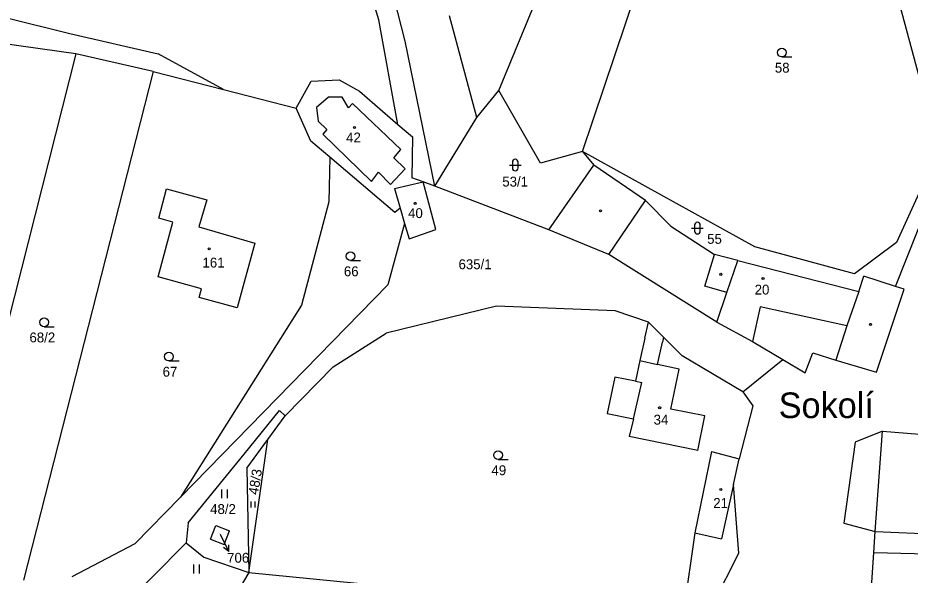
# Model space of a CAD drawing. Extents: x -654459 to -653618, y -1151040 to -1150446.
# Drawn here: x -654178.6 to -654025.1, y -1150881.9 to -1150786 of the extents above; entities that cross this region are included whole.
import ezdxf

# ---------------------------------------------------------------- set-up
doc = ezdxf.new("R2010")
doc.units = 0
for name, color, linetype in [('Vrstva 1', 7, 'Continuous'), ('Vrstva 13', 7, 'Continuous'), ('Vrstva 2', 7, 'Continuous'), ('Vrstva 3', 7, 'Continuous'), ('Vrstva 4', 7, 'Continuous'), ('Vrstva 5', 7, 'Continuous'), ('Vrstva 7', 7, 'Continuous')]:
    doc.layers.add(name, color=color, linetype=linetype)

msp = doc.modelspace()

# ---------------------------------------------------------------- linework, layer by layer
at = {"layer": 'Vrstva 1'}
for points in [[(-654309.16, -1150753.96), (-654169.59, -1150788.7)], [(-654111.94, -1150790.03), (-654117.57, -1150767.99)], [(-654116.45, -1150786.36), (-654121.45, -1150769.94)], [(-654081.45, -1150808.97), (-654068.36, -1150770.11)], [(-654095.8, -1150798.49), (-654088.98, -1150781.92)], [(-654021.7, -1150802.89), (-654026.75, -1150784.17)], [(-654113.16, -1150804.35), (-654116.45, -1150786.36)], [(-654099.58, -1150803.17), (-654104.28, -1150785.64)], [(-654169.59, -1150788.7), (-654154.41, -1150792.18)], [(-654168.58, -1150792.21), (-654181.23, -1150790.41)], [(-654106.85, -1150814.94), (-654111.94, -1150790.03)], [(-654168.58, -1150792.21), (-654186.2, -1150861.52)], [(-654155.27, -1150795.25), (-654168.58, -1150792.21)], [(-654143.15, -1150798.35), (-654154.41, -1150792.18)], [(-654155.27, -1150795.25), (-654177.57, -1150882.76)], [(-654155.27, -1150795.25), (-654143.15, -1150798.35)], [(-654130.65, -1150801.54), (-654128.09, -1150796.9)], [(-654128.09, -1150796.9), (-654123.29, -1150796.64)], [(-654123.29, -1150796.64), (-654119.76, -1150798.64)], [(-654143.15, -1150798.35), (-654130.65, -1150801.54)], [(-654119.76, -1150798.64), (-654113.16, -1150804.35)], [(-654099.58, -1150803.17), (-654095.8, -1150798.49)], [(-654088.62, -1150811.01), (-654095.8, -1150798.49)], [(-654128.14, -1150807.23), (-654130.65, -1150801.54)], [(-654106.85, -1150814.94), (-654099.58, -1150803.17)], [(-654113.16, -1150804.35), (-654110.68, -1150806.5)], [(-654110.68, -1150806.5), (-654110.79, -1150813.55)], [(-654124.87, -1150810), (-654128.14, -1150807.23)], [(-654020.03, -1150808.4), (-654027.41, -1150824.64)], [(-654081.45, -1150808.97), (-654088.62, -1150811.01)], [(-654051.79, -1150825.38), (-654081.45, -1150808.97)], [(-654081.45, -1150808.97), (-654079.5, -1150811.32)], [(-654027.56, -1150832.2), (-654018.25, -1150808.73)], [(-654124.87, -1150810), (-654125.04, -1150817.67)], [(-654113.68, -1150819.5), (-654124.87, -1150810)], [(-654087.23, -1150822.49), (-654079.5, -1150811.32)], [(-654070.58, -1150817.41), (-654079.5, -1150811.32)], [(-654113.77, -1150815.37), (-654108.85, -1150814.2)], [(-654108.85, -1150814.2), (-654110.79, -1150813.55)], [(-654106.63, -1150822.43), (-654108.85, -1150814.2)], [(-654106.85, -1150814.94), (-654108.85, -1150814.2)], [(-654154.32, -1150820.47), (-654152.98, -1150815.43)], [(-654152.98, -1150815.43), (-654146.07, -1150817.3)], [(-654113.77, -1150815.37), (-654112.79, -1150818.74)], [(-654087.23, -1150822.49), (-654106.85, -1150814.94)], [(-654146.07, -1150817.3), (-654147.44, -1150821.94)], [(-654070.58, -1150817.41), (-654066.24, -1150821.87)], [(-654125.04, -1150817.67), (-654129.75, -1150835.46)], [(-654112.79, -1150818.74), (-654113.68, -1150819.5)], [(-654112.79, -1150818.74), (-654112.02, -1150821.38)], [(-654151.9, -1150821.13), (-654154.32, -1150820.47)], [(-654154.44, -1150830.58), (-654151.9, -1150821.13)], [(-654147.44, -1150821.94), (-654137.76, -1150824.79)], [(-654112.02, -1150821.38), (-654114.9, -1150831.92)], [(-654112.02, -1150821.38), (-654111.24, -1150824.03)], [(-654066.24, -1150821.87), (-654058.69, -1150826.71)], [(-654111.24, -1150824.03), (-654106.63, -1150822.43)], [(-654076.92, -1150826.7), (-654087.23, -1150822.49)], [(-654137.76, -1150824.79), (-654140.8, -1150835.92)], [(-654027.41, -1150824.64), (-654034.63, -1150830.06)], [(-654058.32, -1150838.34), (-654076.92, -1150826.7)], [(-654054.69, -1150827.74), (-654058.69, -1150826.71)], [(-654034.63, -1150830.06), (-654051.79, -1150825.38)], [(-654054.69, -1150827.74), (-654033.91, -1150833.09)], [(-654146.96, -1150832.63), (-654154.44, -1150830.58)], [(-654033.91, -1150833.09), (-654033.02, -1150830.45)], [(-654027.56, -1150832.2), (-654033.02, -1150830.45)], [(-654114.9, -1150831.92), (-654150.57, -1150868.48)], [(-654147.35, -1150834.1), (-654146.96, -1150832.63)], [(-654030.83, -1150846.98), (-654026.12, -1150832.7)], [(-654026.12, -1150832.7), (-654027.56, -1150832.2)], [(-654140.8, -1150835.92), (-654147.35, -1150834.1)], [(-654129.75, -1150835.46), (-654150.57, -1150868.48)], [(-654096.24, -1150835.59), (-654115.19, -1150840.24)], [(-654075.8, -1150836.41), (-654096.24, -1150835.59)], [(-654070.09, -1150838.34), (-654075.8, -1150836.41)], [(-654070.7, -1150841.13), (-654070.09, -1150838.34)], [(-654070.09, -1150838.34), (-654067.48, -1150840.96)], [(-654058.32, -1150838.34), (-654052.21, -1150841.67)], [(-654124.32, -1150846.07), (-654115.19, -1150840.24)], [(-654070.7, -1150841.13), (-654071.54, -1150844.98)], [(-654068.5, -1150845.64), (-654067.66, -1150841.79)], [(-654067.48, -1150840.96), (-654067.66, -1150841.79)], [(-654067.48, -1150840.96), (-654064.28, -1150844.18)], [(-654052.21, -1150841.67), (-654046.97, -1150844.79)], [(-654043.1, -1150847.09), (-654041.8, -1150843.63)], [(-654041.8, -1150843.63), (-654037.86, -1150844.88)], [(-654071.54, -1150844.98), (-654072.32, -1150848.54)], [(-654053.85, -1150850.35), (-654064.28, -1150844.18)], [(-654053.85, -1150850.35), (-654046.97, -1150844.79)], [(-654046.97, -1150844.79), (-654043.1, -1150847.09)], [(-654037.86, -1150844.88), (-654030.83, -1150846.98)], [(-654132.59, -1150854.45), (-654124.32, -1150846.07)], [(-654064.77, -1150846.44), (-654068.5, -1150845.64)], [(-654066.25, -1150853.31), (-654064.77, -1150846.44)], [(-654075.89, -1150847.81), (-654077.17, -1150854.09)], [(-654072.32, -1150848.54), (-654075.89, -1150847.81)], [(-654053.85, -1150850.35), (-654052.1, -1150852.78)], [(-654052.1, -1150852.78), (-654054.47, -1150861.9)], [(-654139.6, -1150861.05), (-654133.55, -1150853.57)], [(-654135.57, -1150858.56), (-654132.59, -1150854.45)], [(-654133.55, -1150853.57), (-654132.59, -1150854.45)], [(-654077.17, -1150854.09), (-654072.67, -1150855.01)], [(-654060.37, -1150854.49), (-654066.25, -1150853.31)], [(-654072.67, -1150855.01), (-654073.37, -1150858.06)], [(-654061.57, -1150860.44), (-654060.37, -1150854.49)], [(-654029.83, -1150857.12), (-654034.52, -1150859)], [(-654029.83, -1150857.12), (-654002.97, -1150859.28)], [(-654139.15, -1150863.5), (-654135.57, -1150858.56)], [(-654138.81, -1150881.42), (-654135.57, -1150858.56)], [(-654061.57, -1150860.44), (-654073.37, -1150858.06)], [(-654034.52, -1150859), (-654036.45, -1150872.93)], [(-654149.26, -1150872.9), (-654139.6, -1150861.05)], [(-654059.26, -1150860.62), (-654062.12, -1150874.59)], [(-654059.26, -1150860.62), (-654054.47, -1150861.9)], [(-654055.44, -1150866.28), (-654054.47, -1150861.9)], [(-654139.15, -1150863.5), (-654138.81, -1150881.42)], [(-654054.51, -1150878.1), (-654055.44, -1150866.28)], [(-654150.57, -1150868.48), (-654158.41, -1150876.51)], [(-654149.26, -1150872.9), (-654149.58, -1150876.33)], [(-654145.42, -1150875.69), (-654144.49, -1150873.34)], [(-654144.49, -1150873.34), (-654142.14, -1150874.27)], [(-654143.07, -1150876.62), (-654142.14, -1150874.27)], [(-654036.45, -1150872.93), (-654031.11, -1150874.37)], [(-654031.34, -1150877.98), (-654031.11, -1150874.37)], [(-654145.42, -1150875.69), (-654143.07, -1150876.62)], [(-654062.12, -1150874.59), (-654064.01, -1150887.81)], [(-654158.41, -1150876.51), (-654169.24, -1150882.2)], [(-654161.43, -1150888.26), (-654149.58, -1150876.33)], [(-654149.58, -1150876.33), (-654146.57, -1150878.79)], [(-654146.57, -1150878.79), (-654138.81, -1150881.42)], [(-654058.94, -1150886.81), (-654054.51, -1150878.1)], [(-654031.95, -1150887.48), (-654031.34, -1150877.98)], [(-654031.34, -1150877.98), (-654015, -1150878.38)], [(-654138.81, -1150881.42), (-654140.8, -1150884.84)], [(-654138.81, -1150881.42), (-654105.61, -1150884.7)]]:
    msp.add_lwpolyline(points, dxfattribs=at)
at = {"layer": 'Vrstva 3'}
for p, q in [((-654047.14, -1150792.73), (-654045.39, -1150792.73)), ((-654093.99, -1150811.33), (-654091.99, -1150811.33)), ((-654093.49, -1150810.83), (-654093.49, -1150811.83)), ((-654092.49, -1150811.83), (-654092.49, -1150810.83)), ((-654062.66, -1150822.18), (-654060.66, -1150822.18)), ((-654062.16, -1150821.68), (-654062.16, -1150822.68)), ((-654061.16, -1150822.68), (-654061.16, -1150821.68)), ((-654121.34, -1150827.76), (-654119.59, -1150827.76)), ((-654174.03, -1150839.14), (-654172.28, -1150839.14)), ((-654152.56, -1150845.04), (-654150.81, -1150845.04)), ((-654095.95, -1150861.99), (-654094.2, -1150861.99)), ((-654143.47, -1150868.67), (-654143.47, -1150867.17)), ((-654142.47, -1150868.67), (-654142.47, -1150867.17)), ((-654138.39, -1150870.23), (-654138.39, -1150869.23)), ((-654137.72, -1150870.23), (-654137.72, -1150869.23)), ((-654148.28, -1150881.58), (-654148.28, -1150880.08)), ((-654147.28, -1150881.58), (-654147.28, -1150880.08))]:
    msp.add_line(p, q, dxfattribs=at)
for centre in [(-654047.14, -1150791.98), (-654121.34, -1150827.01), (-654174.03, -1150838.39), (-654152.56, -1150844.29), (-654095.95, -1150861.24)]:
    msp.add_circle(centre, 0.75, dxfattribs=at)
for centre, start, end in [((-654092.99, -1150810.83), 0, 180), ((-654092.99, -1150811.83), 180, 359.9879), ((-654061.66, -1150821.68), 0, 180), ((-654061.66, -1150822.68), 180, 359.9879)]:
    msp.add_arc(centre, 0.5, start, end, dxfattribs=at)
at = {"layer": 'Vrstva 4'}
for points in [[(-654125.09, -1150799.64), (-654127.19, -1150801.45)], [(-654122.74, -1150799.66), (-654125.09, -1150799.64)], [(-654121.67, -1150801.47), (-654122.74, -1150799.66)], [(-654127.19, -1150801.45), (-654126.91, -1150803.78)], [(-654120.98, -1150800.75), (-654121.67, -1150801.47)], [(-654112.65, -1150808.68), (-654120.98, -1150800.75)], [(-654126.91, -1150803.78), (-654125.4, -1150805.24)], [(-654125.4, -1150805.24), (-654126.07, -1150805.99)], [(-654126.07, -1150805.99), (-654117.73, -1150814.15)], [(-654113.9, -1150810.06), (-654112.65, -1150808.68)], [(-654111.9, -1150811.98), (-654113.9, -1150810.06)], [(-654117.73, -1150814.15), (-654116.49, -1150812.57)], [(-654116.49, -1150812.57), (-654114.45, -1150814.67)], [(-654114.45, -1150814.67), (-654111.9, -1150811.98)], [(-654076.92, -1150826.7), (-654070.58, -1150817.41)], [(-654060.4, -1150832.18), (-654058.69, -1150826.71)], [(-654056.58, -1150833.25), (-654054.69, -1150827.74)], [(-654056.58, -1150833.25), (-654060.4, -1150832.18)], [(-654058.32, -1150838.34), (-654056.58, -1150833.25)], [(-654033.91, -1150833.09), (-654035.94, -1150839.01)], [(-654050.86, -1150835.71), (-654052.21, -1150841.67)], [(-654035.94, -1150839.01), (-654050.86, -1150835.71)], [(-654035.94, -1150839.01), (-654037.86, -1150844.88)], [(-654071.54, -1150844.98), (-654068.5, -1150845.64)], [(-654072.67, -1150855.01), (-654071.24, -1150848.77)], [(-654072.32, -1150848.54), (-654071.24, -1150848.77)], [(-654031.11, -1150874.37), (-654029.83, -1150857.12)], [(-654055.44, -1150866.28), (-654057.5, -1150875.63)], [(-654031.11, -1150874.37), (-654020.25, -1150874.82)], [(-654062.12, -1150874.59), (-654057.5, -1150875.63)]]:
    msp.add_lwpolyline(points, dxfattribs=at)
at = {"layer": 'Vrstva 5'}
for centre in [(-654120.66, -1150804.85), (-654110.22, -1150817.92), (-654078.34, -1150819.19), (-654145.64, -1150825.73), (-654057.64, -1150830.13), (-654050.37, -1150830.83), (-654031.89, -1150838.74), (-654068.15, -1150853.08), (-654057.63, -1150867.16)]:
    msp.add_circle(centre, 0.175, dxfattribs=at)
at = {"layer": 'Vrstva 7'}
for p, q in [((-654143.61, -1150875.12), (-654142.27, -1150877.81)), ((-654142.27, -1150877.81), (-654143.17, -1150877.13)), ((-654142.27, -1150877.81), (-654142.27, -1150876.69))]:
    msp.add_line(p, q, dxfattribs=at)
msp.add_lwpolyline([(-654143.75, -1150874.84), (-654143.61, -1150875.12)], dxfattribs=at)

# ---------------------------------------------------------------- texts
at = {"layer": 'Vrstva 13'}
for s, p in [('42', (-654122.08, -1150807.44)), ('40', (-654111.42, -1150820.45)), ('161', (-654146.79, -1150828.96)), ('20', (-654051.81, -1150833.61)), ('34', (-654069.19, -1150855.99)), ('21', (-654058.93, -1150870.32))]:
    msp.add_text(s, height=1.7, dxfattribs=at).set_placement(p)
at = {"layer": 'Vrstva 2'}
for s, height, p in [('58', 1.7, (-654048.33, -1150795.43)), ('53/1', 1.7, (-654095.22, -1150815.03)), ('55', 1.7, (-654059.98, -1150824.88)), ('635/1', 1.7, (-654102.75, -1150829.25)), ('66', 1.7, (-654122.47, -1150830.46)), ('68/2', 1.7, (-654176.55, -1150841.84)), ('67', 1.7, (-654153.65, -1150847.74)), ('49', 1.7, (-654097.08, -1150864.69)), ('48/2', 1.7, (-654145.47, -1150871.37)), ('706', 0.1, (-654143.85, -1150874.84))]:
    msp.add_text(s, height=height, dxfattribs=at).set_placement(p)
msp.add_text('48/3', height=1.7, rotation=80.9458, dxfattribs=at).set_placement((-654137.24, -1150868.15))
at = {"layer": 'Vrstva 7'}
for s, height, p in [('Sokolí', 4.4, (-654047.67, -1150854.86)), ('706', 1.7, (-654142.55, -1150879.75)), ('706', 1.7, (-654142.55, -1150879.75)), ('706', 1.7, (-654142.55, -1150879.75)), ('706', 1.7, (-654142.55, -1150879.75))]:
    msp.add_text(s, height=height, dxfattribs=at).set_placement(p)

doc.saveas('drawing.dxf')
